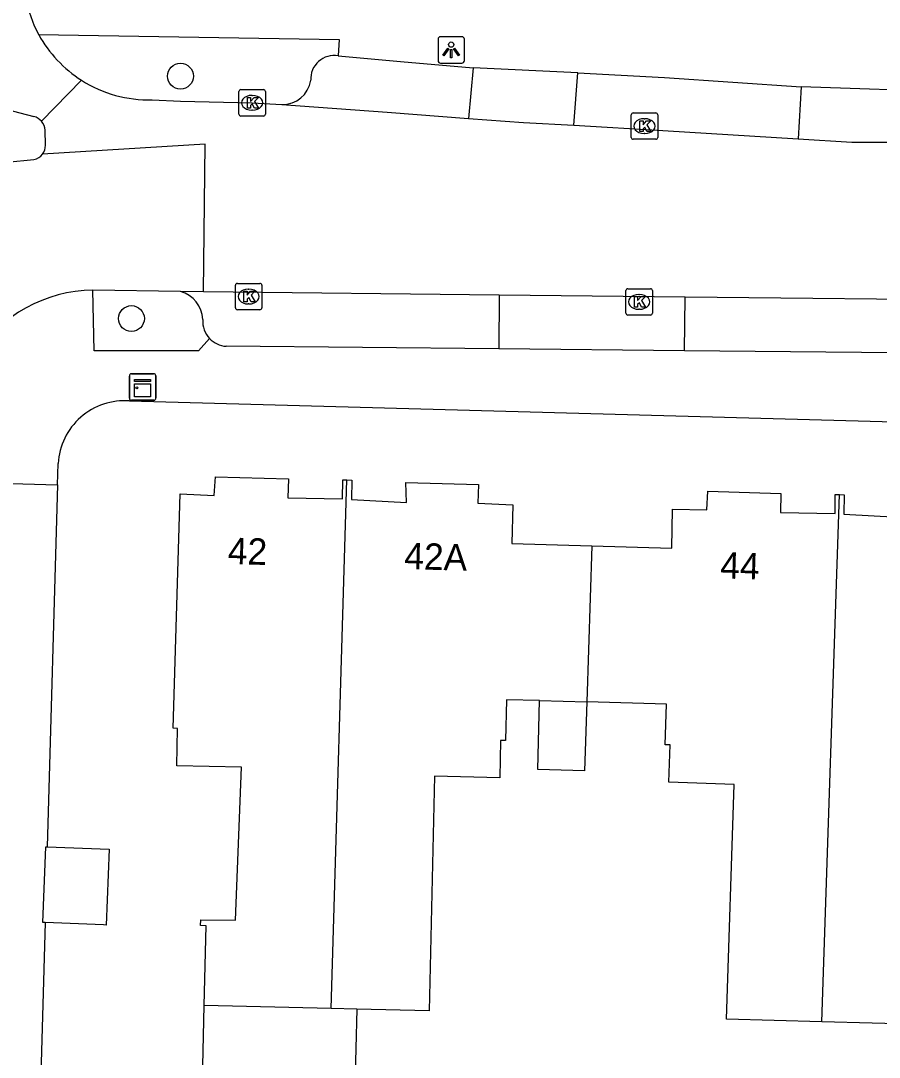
# Model space of a CAD drawing. Extents: x 162082 to 163393, y 388091 to 388632.
# Drawn here: x 162543.15 to 162575.64, y 388432.17 to 388471.39 of the extents above; entities that cross this region are included whole.
import ezdxf

# ---------------------------------------------------------------- set-up
doc = ezdxf.new("R2010")
doc.units = 0
for name, color, linetype in [('IMGEO_Boom', 7, 'Continuous'), ('IMGEO_Fietspad_gesloten', 7, 'Continuous'), ('IMGEO_Kast', 7, 'Continuous'), ('IMGEO_Kolk', 7, 'Continuous'), ('IMGEO_Lichtpunt', 7, 'Continuous'), ('IMGEO_Pand', 7, 'Continuous'), ('IMGEO_Pand_nummerreeks', 7, 'Continuous'), ('IMGEO_Parkeervlak_open', 7, 'Continuous'), ('IMGEO_Rijbaan_lokaal_gesloten', 7, 'Continuous'), ('IMGEO_Rijbaan_lokaal_open', 7, 'Continuous'), ('IMGEO_Voetpad_open', 7, 'Continuous')]:
    doc.layers.add(name, color=color, linetype=linetype)

msp = doc.modelspace()

# ---------------------------------------------------------------- linework, layer by layer
at = {"layer": 'IMGEO_Boom'}
for centre in [(162549.192, 388469.291), (162547.336, 388460.118)]:
    msp.add_circle(centre, 0.489, dxfattribs=at)
at = {"layer": 'IMGEO_Fietspad_gesloten'}
msp.add_lwpolyline([(162542.043, 388468.185), (162543.647, 388467.76)], dxfattribs=at)
for centre, radius, start, end in [((162547.675, 388472.97), 4.388, 189.3096, 208.6657), ((162548.011, 388473.169), 4.778, 208.8324, 237.6198), ((162543.51, 388467.215), 0.562, 41.0463, 75.917)]:
    msp.add_arc(centre, radius, start, end, dxfattribs=at)
at = {"layer": 'IMGEO_Kast'}
for p, q in [((162547.261, 388457.104), (162547.261, 388457.945)), ((162547.261, 388457.945), (162547.261, 388457.104)), ((162547.336, 388458.029), (162548.177, 388458.029)), ((162548.177, 388458.029), (162547.336, 388458.029)), ((162548.261, 388457.954), (162548.261, 388457.113)), ((162548.261, 388457.113), (162548.261, 388457.954)), ((162548.186, 388457.029), (162547.345, 388457.029)), ((162547.345, 388457.029), (162548.186, 388457.029))]:
    msp.add_line(p, q, dxfattribs=at)
for points in [[(162547.456, 388457.819), (162548.056, 388457.819), (162548.056, 388457.734), (162547.456, 388457.734), (162547.456, 388457.819)], [(162547.456, 388457.644), (162548.056, 388457.644), (162548.056, 388457.155), (162547.456, 388457.155), (162547.456, 388457.644)]]:
    msp.add_lwpolyline(points, dxfattribs=at)
msp.add_circle((162547.54, 388457.493), 0.0377, dxfattribs=at)
for centre, start, end in [((162547.339, 388457.951), 92.4484, 184.2845), ((162547.339, 388457.951), 92.4484, 184.2845), ((162548.183, 388457.951), 2.4484, 94.2845), ((162548.183, 388457.951), 2.4484, 94.2845), ((162547.339, 388457.107), 182.4484, 274.2845), ((162547.339, 388457.107), 182.4484, 274.2845), ((162548.183, 388457.107), 272.4484, 4.2845), ((162548.183, 388457.107), 272.4484, 4.2845)]:
    msp.add_arc(centre, 0.0779, start, end, dxfattribs=at)
at = {"layer": 'IMGEO_Kolk'}
for p, q in [((162551.479, 388468.783), (162552.331, 388468.783)), ((162551.404, 388467.857), (162551.404, 388468.709)), ((162551.892, 388468.563), (162551.917, 388468.563)), ((162552.405, 388468.709), (162552.405, 388467.857)), ((162551.915, 388468.003), (162551.89, 388468.003)), ((162552.331, 388467.783), (162551.479, 388467.783)), ((162566.256, 388466.976), (162566.256, 388467.828)), ((162566.331, 388467.902), (162567.183, 388467.902)), ((162566.744, 388467.682), (162566.769, 388467.682)), ((162567.257, 388467.828), (162567.257, 388466.976)), ((162567.183, 388466.902), (162566.331, 388466.902)), ((162566.767, 388467.122), (162566.742, 388467.122)), ((162551.272, 388460.525), (162551.272, 388461.377)), ((162551.347, 388461.451), (162552.199, 388461.451)), ((162552.273, 388461.377), (162552.273, 388460.525)), ((162551.76, 388461.231), (162551.785, 388461.231)), ((162566.054, 388460.323), (162566.054, 388461.175)), ((162566.129, 388461.249), (162566.981, 388461.249)), ((162566.542, 388461.029), (162566.567, 388461.029)), ((162567.055, 388461.175), (162567.055, 388460.323)), ((162551.783, 388460.671), (162551.758, 388460.671)), ((162552.199, 388460.451), (162551.347, 388460.451)), ((162566.981, 388460.249), (162566.129, 388460.249)), ((162566.565, 388460.469), (162566.54, 388460.469))]:
    msp.add_line(p, q, dxfattribs=at)
for points in [[(162551.479, 388468.783), (162552.331, 388468.783)], [(162551.404, 388467.857), (162551.404, 388468.709)], [(162551.725, 388468.483), (162551.848, 388468.483), (162551.848, 388468.332), (162551.978, 388468.483), (162552.142, 388468.483), (162551.996, 388468.332), (162552.149, 388468.083), (162551.997, 388468.083), (162551.912, 388468.247), (162551.848, 388468.18), (162551.848, 388468.083), (162551.725, 388468.083), (162551.725, 388468.483)], [(162552.405, 388468.709), (162552.405, 388467.857)], [(162552.331, 388467.783), (162551.479, 388467.783)], [(162566.256, 388466.976), (162566.256, 388467.828)], [(162566.331, 388467.902), (162567.183, 388467.902)], [(162566.577, 388467.602), (162566.7, 388467.602), (162566.7, 388467.451), (162566.83, 388467.602), (162566.994, 388467.602), (162566.848, 388467.451), (162567.001, 388467.202), (162566.849, 388467.202), (162566.764, 388467.366), (162566.7, 388467.299), (162566.7, 388467.202), (162566.577, 388467.202), (162566.577, 388467.602)], [(162567.257, 388467.828), (162567.257, 388466.976)], [(162567.183, 388466.902), (162566.331, 388466.902)], [(162551.272, 388460.525), (162551.272, 388461.377)], [(162551.347, 388461.451), (162552.199, 388461.451)], [(162552.273, 388461.377), (162552.273, 388460.525)], [(162551.593, 388461.151), (162551.716, 388461.151), (162551.716, 388461), (162551.846, 388461.151), (162552.01, 388461.151), (162551.864, 388461), (162552.017, 388460.751), (162551.865, 388460.751), (162551.78, 388460.915), (162551.716, 388460.848), (162551.716, 388460.751), (162551.593, 388460.751), (162551.593, 388461.151)], [(162566.054, 388460.323), (162566.054, 388461.175)], [(162566.129, 388461.249), (162566.981, 388461.249)], [(162566.375, 388460.949), (162566.498, 388460.949), (162566.498, 388460.798), (162566.628, 388460.949), (162566.792, 388460.949), (162566.646, 388460.798), (162566.799, 388460.549), (162566.647, 388460.549), (162566.562, 388460.713), (162566.498, 388460.646), (162566.498, 388460.549), (162566.375, 388460.549), (162566.375, 388460.949)], [(162567.055, 388461.175), (162567.055, 388460.323)], [(162552.199, 388460.451), (162551.347, 388460.451)], [(162566.981, 388460.249), (162566.129, 388460.249)]]:
    msp.add_lwpolyline(points, dxfattribs=at)
for centre, start, end in [((162551.481, 388468.707), 91.552, 178.448), ((162551.481, 388468.707), 91.552, 178.448), ((162552.329, 388468.707), 1.552, 88.448), ((162552.329, 388468.707), 1.552, 88.448), ((162551.481, 388467.859), 181.552, 268.448), ((162551.481, 388467.859), 181.552, 268.448), ((162552.329, 388467.859), 271.552, 358.448), ((162552.329, 388467.859), 271.552, 358.448), ((162566.333, 388467.826), 91.552, 178.448), ((162566.333, 388467.826), 91.552, 178.448), ((162567.181, 388467.826), 1.552, 88.448), ((162567.181, 388467.826), 1.552, 88.448), ((162566.333, 388466.978), 181.552, 268.448), ((162566.333, 388466.978), 181.552, 268.448), ((162567.181, 388466.978), 271.552, 358.448), ((162567.181, 388466.978), 271.552, 358.448), ((162551.349, 388461.375), 91.552, 178.448), ((162551.349, 388461.375), 91.552, 178.448), ((162552.197, 388461.375), 1.552, 88.448), ((162552.197, 388461.375), 1.552, 88.448), ((162566.131, 388461.173), 91.552, 178.448), ((162566.131, 388461.173), 91.552, 178.448), ((162566.979, 388461.173), 1.552, 88.448), ((162566.979, 388461.173), 1.552, 88.448), ((162551.349, 388460.527), 181.552, 268.448), ((162551.349, 388460.527), 181.552, 268.448), ((162552.197, 388460.527), 271.552, 358.448), ((162552.197, 388460.527), 271.552, 358.448), ((162566.131, 388460.325), 181.552, 268.448), ((162566.131, 388460.325), 181.552, 268.448), ((162566.979, 388460.325), 271.552, 358.448), ((162566.979, 388460.325), 271.552, 358.448)]:
    msp.add_arc(centre, 0.0765, start, end, dxfattribs=at)
for centre, major_axis, ratio, start_param, end_param in [((162551.891, 388468.283), (-0.387, 0.002), 0.722429, 4.712389, 7.853982), ((162551.916, 388468.283), (-0.39, 0.002), 0.717154, 1.570796, 4.712389), ((162566.743, 388467.402), (-0.387, 0.002), 0.722429, 4.712389, 7.853982), ((162566.768, 388467.402), (-0.39, 0.002), 0.717154, 1.570796, 4.712389), ((162551.759, 388460.951), (-0.387, 0.002), 0.722429, 4.712389, 7.853982), ((162551.784, 388460.951), (-0.39, 0.002), 0.717154, 1.570796, 4.712389), ((162566.541, 388460.749), (-0.387, 0.002), 0.722429, 4.712389, 7.853982), ((162566.566, 388460.749), (-0.39, 0.002), 0.717154, 1.570796, 4.712389)]:
    msp.add_ellipse(centre, major_axis=major_axis, ratio=ratio, start_param=start_param, end_param=end_param, dxfattribs=at)
at = {"layer": 'IMGEO_Lichtpunt'}
for p, q in [((162558.942, 388470.687), (162558.942, 388469.88)), ((162558.942, 388470.687), (162558.942, 388469.88)), ((162559.844, 388470.782), (162559.036, 388470.782)), ((162559.844, 388470.782), (162559.036, 388470.782)), ((162559.938, 388469.88), (162559.938, 388470.687)), ((162559.938, 388469.88), (162559.938, 388470.687)), ((162559.036, 388469.786), (162559.844, 388469.786)), ((162559.036, 388469.786), (162559.844, 388469.786))]:
    msp.add_line(p, q, dxfattribs=at)
for points in [[(162559.316, 388470.351), (162559.355, 388470.323), (162559.167, 388470.061), (162559.129, 388470.088), (162559.316, 388470.351)], [(162559.418, 388470.303), (162559.465, 388470.303), (162559.465, 388469.981), (162559.418, 388469.981), (162559.418, 388470.303)], [(162559.528, 388470.323), (162559.566, 388470.35), (162559.753, 388470.088), (162559.714, 388470.06), (162559.528, 388470.323)]]:
    msp.add_lwpolyline(points, dxfattribs=at)
msp.add_circle((162559.441, 388470.485), 0.0994, dxfattribs=at)
for centre, start, end in [((162559.036, 388470.687), 90, 180), ((162559.036, 388470.687), 90, 180), ((162559.844, 388470.687), 0, 90), ((162559.844, 388470.687), 0, 90), ((162559.036, 388469.88), 180, 270), ((162559.036, 388469.88), 180, 270), ((162559.844, 388469.88), 270, 0), ((162559.844, 388469.88), 270, 360)]:
    msp.add_arc(centre, 0.0946, start, end, dxfattribs=at)
at = {"layer": 'IMGEO_Pand'}
for points in [[(162550.095, 388434.125), (162550.168, 388437.14), (162549.951, 388437.152), (162549.96, 388437.368), (162551.28, 388437.35), (162551.5, 388443.144), (162549.053, 388443.2), (162549.085, 388444.61), (162548.919, 388444.614), (162549.183, 388453.489), (162550.465, 388453.43), (162550.52, 388454.132), (162553.283, 388454.049), (162553.262, 388453.334), (162555.331, 388453.292), (162555.335, 388454.017), (162555.49, 388454.012)], [(162554.898, 388434.009), (162555.49, 388454.012)], [(162555.49, 388454.012), (162555.68, 388454.005), (162555.662, 388453.272), (162557.746, 388453.156), (162557.729, 388453.92), (162560.471, 388453.845), (162560.451, 388453.128), (162561.774, 388453.074), (162561.73, 388451.603), (162564.763, 388451.517)], [(162564.763, 388451.517), (162567.79, 388451.432), (162567.811, 388452.911), (162569.121, 388452.882), (162569.157, 388453.582), (162571.92, 388453.499), (162571.899, 388452.784), (162573.968, 388452.742), (162573.972, 388453.467), (162574.136, 388453.461)], [(162573.472, 388433.511), (162574.136, 388453.461)], [(162574.136, 388453.461), (162574.317, 388453.455), (162574.299, 388452.722), (162576.371, 388452.607), (162576.368, 388453.367), (162579.126, 388453.272), (162579.114, 388452.579), (162580.435, 388452.512), (162580.391, 388451.033), (162583.409, 388450.957)], [(162564.763, 388451.517), (162564.573, 388445.615)], [(162562.788, 388445.663), (162561.538, 388445.697), (162561.501, 388444.154), (162561.311, 388444.159), (162561.277, 388442.747), (162558.813, 388442.806), (162558.6, 388433.92), (162555.865, 388433.986)], [(162564.573, 388445.615), (162564.489, 388443.005), (162562.718, 388443.053), (162562.788, 388445.663)], [(162562.788, 388445.663), (162564.573, 388445.615)], [(162573.472, 388433.511), (162569.86, 388433.608), (162570.146, 388442.494), (162567.681, 388442.573), (162567.727, 388443.985), (162567.536, 388443.991), (162567.586, 388445.534), (162564.573, 388445.615)], [(162583.235, 388445.113), (162580.187, 388445.195), (162580.153, 388443.633), (162579.963, 388443.637), (162579.932, 388442.216), (162577.469, 388442.269), (162577.278, 388433.408), (162573.472, 388433.511)], [(162544.069, 388437.261), (162543.984, 388437.264), (162544.093, 388440.135), (162544.152, 388440.133)], [(162544.152, 388440.133), (162546.495, 388440.044), (162546.386, 388437.172), (162546.278, 388437.177), (162544.069, 388437.261)], [(162547.619, 388425.03), (162547.629, 388425.208), (162548.37, 388425.172), (162548.417, 388427.197), (162547.694, 388427.257), (162547.792, 388429.997), (162548.49, 388429.979), (162548.51, 388431.334), (162550.025, 388431.266), (162550.095, 388434.125)], [(162554.898, 388434.009), (162550.095, 388434.125)], [(162555.865, 388433.986), (162554.898, 388434.009)], [(162555.865, 388433.986), (162555.788, 388431.009), (162557.342, 388430.969), (162557.337, 388430.78), (162558.751, 388430.743), (162558.688, 388428.274), (162566.425, 388428.075), (162566.332, 388424.483)]]:
    msp.add_lwpolyline(points, dxfattribs=at)
at = {"layer": 'IMGEO_Parkeervlak_open'}
for centre, radius, start, end in [((162555.018, 388469.177), 0.898, 80.624, 182.7589), ((162553.059, 388469.289), 1.074, 268.3703, 351.6828), ((162548.912, 388460.047), 1.127, 1.9123, 75.5266), ((162550.978, 388460.013), 0.942, 175.6348, 223.6023)]:
    msp.add_arc(centre, radius, start, end, dxfattribs=at)
at = {"layer": 'IMGEO_Rijbaan_lokaal_gesloten'}
for points in [[(162543.934, 388467.584), (162545.452, 388469.134)], [(162548.123, 388468.393), (162549.199, 388468.343), (162551.905, 388468.283), (162553.028, 388468.216)], [(162553.028, 388468.216), (162557.011, 388467.927), (162560.099, 388467.686)], [(162560.099, 388467.686), (162562.172, 388467.535), (162564.078, 388467.441)], [(162544.079, 388466.674), (162544.067, 388467.246)], [(162564.078, 388467.441), (162567.452, 388467.229), (162572.571, 388466.923)], [(162572.571, 388466.923), (162574.61, 388466.79), (162576.691, 388466.789)], [(162550.061, 388461.129), (162550.124, 388466.721), (162543.975, 388466.34)], [(162541.585, 388465.937), (162543.644, 388466.139)], [(162549.194, 388461.139), (162545.878, 388461.195)], [(162550.061, 388461.129), (162549.194, 388461.139)], [(162561.253, 388461.002), (162550.061, 388461.129)], [(162568.295, 388460.934), (162561.253, 388461.002)], [(162580.368, 388460.806), (162568.295, 388460.934)]]:
    msp.add_lwpolyline(points, dxfattribs=at)
for centre, radius, start, end in [((162548.007, 388473.16), 4.769, 237.5986, 271.3908), ((162543.512, 388467.223), 0.555, 2.3829, 40.5755), ((162543.561, 388466.652), 0.519, 323.0076, 2.4016), ((162543.556, 388466.656), 0.525, 279.6054, 322.9311), ((162545.956, 388455.796), 5.4, 90.8248, 146.947)]:
    msp.add_arc(centre, radius, start, end, dxfattribs=at)
at = {"layer": 'IMGEO_Rijbaan_lokaal_open'}
for points in [[(162560.276, 388469.6), (162560.099, 388467.686)], [(162564.232, 388469.415), (162560.276, 388469.6)], [(162564.078, 388467.441), (162564.232, 388469.415)], [(162572.688, 388468.882), (162572.571, 388466.923)], [(162576.745, 388468.747), (162574.537, 388468.822), (162572.688, 388468.882)], [(162561.253, 388461.002), (162561.24, 388458.978)], [(162568.266, 388458.901), (162568.295, 388460.934)], [(162568.266, 388458.901), (162561.24, 388458.978)]]:
    msp.add_lwpolyline(points, dxfattribs=at)
at = {"layer": 'IMGEO_Voetpad_open'}
for points in [[(162543.825, 388470.865), (162555.199, 388470.673), (162555.164, 388470.063)], [(162555.164, 388470.063), (162557.52, 388469.842), (162560.276, 388469.6)], [(162564.232, 388469.415), (162567.512, 388469.236), (162572.688, 388468.882)], [(162550.296, 388459.364), (162549.873, 388458.892), (162545.932, 388458.903), (162545.878, 388461.195)], [(162561.24, 388458.978), (162550.921, 388459.07)], [(162580.325, 388458.784), (162568.266, 388458.901)], [(162547.269, 388457.001), (162601.04, 388455.529)], [(162544.543, 388453.83), (162544.566, 388454.63)], [(162540.163, 388453.955), (162544.543, 388453.83)], [(162544.543, 388453.83), (162544.152, 388440.133)], [(162544.069, 388437.261), (162542.31, 388375.7)]]:
    msp.add_lwpolyline(points, dxfattribs=at)
for centre, radius, start, end in [((162550.985, 388460.017), 0.949, 223.4591, 266.1563), ((162547.071, 388454.5), 2.509, 85.4823, 177.0305)]:
    msp.add_arc(centre, radius, start, end, dxfattribs=at)

# ---------------------------------------------------------------- texts
at = {"layer": 'IMGEO_Pand_nummerreeks'}
for s, rotation, p in [('42', 358.2794, (162550.973, 388450.837)), ('42A', 358.4358, (162557.655, 388450.641)), ('44', 358.2794, (162569.613, 388450.287))]:
    msp.add_text(s, height=1, rotation=rotation, dxfattribs=at).set_placement(p)

doc.saveas('drawing.dxf')
